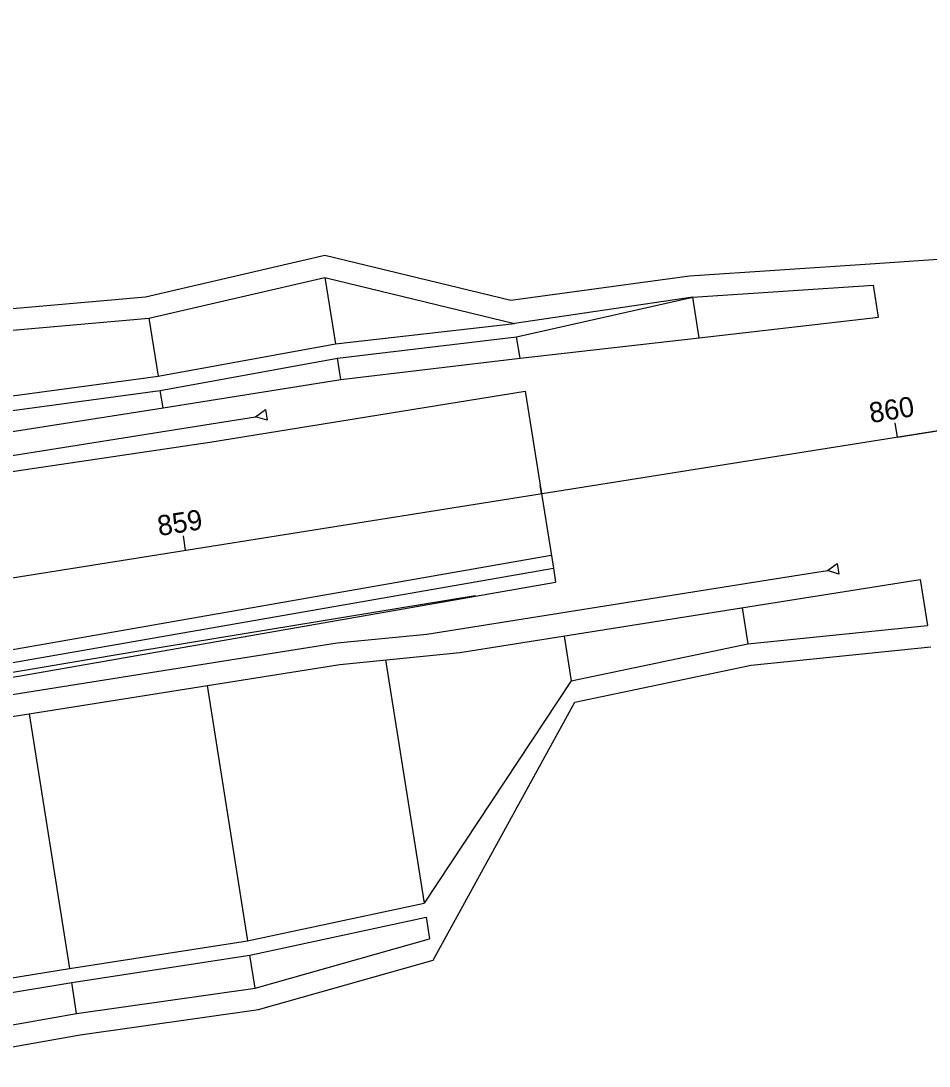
# Model space of a CAD drawing. Extents: x 115987 to 120394, y 324408 to 325987.
# Drawn here: x 117424.6 to 117550.6, y 325408.1 to 325553 of the extents above; entities that cross this region are included whole.
import ezdxf

# ---------------------------------------------------------------- set-up
doc = ezdxf.new("R2010")
doc.units = 0
for name, color, linetype in [('_CIVIL_CONSTRUCTION', 7, 'Continuous'), ('DT_X_Contour_Major', 7, 'Continuous'), ('DT_X_Contour_Minor', 7, 'Continuous'), ('DT_X_Terrain_Boundary', 7, 'Continuous'), ('DT_X_Triangles', 7, 'Continuous'), ('PV_X_EOP', 7, 'Continuous'), ('PV_X_Shoulder', 7, 'Continuous'), ('RW_X_CL_100_Stations', 7, 'Continuous'), ('RW_X_Esmt_LA', 7, 'Continuous'), ('RW_X_Text', 7, 'Continuous'), ('SV_X_Break_Lines', 7, 'Continuous'), ('UT_X_Gas_Cells', 7, 'Continuous')]:
    doc.layers.add(name, color=color, linetype=linetype)

msp = doc.modelspace()

# ---------------------------------------------------------------- linework, layer by layer
at = {"layer": '_CIVIL_CONSTRUCTION'}
msp.add_lwpolyline([(117546.25, 325495.29), (117570.94, 325499.21), (117766.5, 325531.11), (117916.3, 325550), (117982.12, 325552.99), (118061.23, 325550.63), (118140.16, 325542.3), (118267.24, 325523.46), (118330.42, 325512.77)], dxfattribs=at)
at = {"layer": 'DT_X_Contour_Major'}
msp.add_line((117052.43, 325416.91), (117570.94, 325499.21), dxfattribs=at)
at = {"layer": 'DT_X_Contour_Minor'}
for p in [(117498.5, 325477.13), (117400.3, 325457.95)]:
    msp.add_line(p, (117498.82, 325475.16), dxfattribs=at)
at = {"layer": 'DT_X_Terrain_Boundary'}
for p, q in [((117546.25, 325495.29), (117545.93, 325497.26)), ((117496.86, 325487.45), (117496.68, 325488.63)), ((117447.48, 325479.61), (117447.17, 325481.59))]:
    msp.add_line(p, q, dxfattribs=at)
at = {"layer": 'DT_X_Triangles'}
for p, q in [((117494.61, 325501.66), (117496.86, 325487.45)), ((117496.86, 325487.45), (117498.5, 325477.13)), ((117399.7, 325461.7), (117498.22, 325478.91)), ((117399.98, 325459.92), (117498.5, 325477.13))]:
    msp.add_line(p, q, dxfattribs=at)
msp.add_lwpolyline([(117099.65, 325438.36), (117125.38, 325442.42), (117148.92, 325446.09), (117171.45, 325449.83), (117197.23, 325453.75), (117224.14, 325458.05), (117249.57, 325462.07), (117275.34, 325466.27), (117291.59, 325468.95), (117308.28, 325471.78), (117324.97, 325474.61), (117348.76, 325478.42), (117361.44, 325480.5), (117374.12, 325482.58), (117399.9, 325486.47), (117424.04, 325490.6), (117450.84, 325494.57), (117494.61, 325501.66)], dxfattribs=at)
at = {"layer": 'PV_X_EOP'}
for p, q in [((117442.38, 325511.76), (117466.8, 325517.42)), ((117466.8, 325517.42), (117468.26, 325508.22)), ((117466.8, 325517.42), (117493.12, 325511.04)), ((117518.75, 325509.05), (117517.85, 325514.68)), ((117417.41, 325509.58), (117442.38, 325511.76)), ((117442.38, 325511.76), (117443.66, 325503.71)), ((117518.75, 325509.05), (117543.61, 325511.89)), ((117493.88, 325506.21), (117493.41, 325509.18)), ((117493.88, 325506.21), (117518.75, 325509.05)), ((117469.04, 325503.28), (117468.57, 325506.25)), ((117469.04, 325503.28), (117493.88, 325506.21)), ((117444.35, 325499.36), (117469.04, 325503.28)), ((117444.35, 325499.36), (117443.97, 325501.74)), ((117419.66, 325495.45), (117444.35, 325499.36)), ((117485.51, 325465.4), (117549.38, 325475.53)), ((117524.69, 325471.62), (117525.48, 325466.63)), ((117525.48, 325466.63), (117550.39, 325469.15)), ((117500, 325467.7), (117500.99, 325461.49)), ((117468.89, 325463.77), (117485.51, 325465.4)), ((117500.99, 325461.49), (117525.48, 325466.63)), ((117475.21, 325464.39), (117480.56, 325430.68)), ((117234.5, 325426.57), (117468.89, 325463.77)), ((117500.99, 325461.49), (117480.56, 325430.68)), ((117450.46, 325460.85), (117456.08, 325425.43)), ((117425.77, 325456.93), (117431.37, 325421.62)), ((117480.87, 325428.71), (117481.34, 325425.74)), ((117457.12, 325418.86), (117481.34, 325425.74)), ((117457.12, 325418.86), (117456.39, 325423.45)), ((117432.37, 325415.35), (117431.68, 325419.64)), ((117432.37, 325415.35), (117457.12, 325418.86)), ((117407.74, 325411.03), (117432.37, 325415.35))]:
    msp.add_line(p, q, dxfattribs=at)
at = {"layer": 'PV_X_Shoulder'}
for p, q in [((117517.85, 325514.68), (117542.9, 325516.35)), ((117517.85, 325514.68), (117493.12, 325511.04)), ((117493.41, 325509.18), (117517.85, 325514.68)), ((117468.26, 325508.22), (117493.12, 325511.04)), ((117468.57, 325506.25), (117493.41, 325509.18)), ((117443.66, 325503.71), (117468.26, 325508.22)), ((117443.97, 325501.74), (117468.57, 325506.25)), ((117418.87, 325500.38), (117443.66, 325503.71)), ((117419.19, 325498.41), (117443.97, 325501.74)), ((117456.08, 325425.43), (117480.56, 325430.68)), ((117456.39, 325423.45), (117480.87, 325428.71)), ((117431.37, 325421.62), (117456.08, 325425.43)), ((117431.68, 325419.64), (117456.39, 325423.45)), ((117406.71, 325417.56), (117431.37, 325421.62)), ((117407.02, 325415.59), (117431.68, 325419.64))]:
    msp.add_line(p, q, dxfattribs=at)
at = {"layer": 'RW_X_CL_100_Stations'}
for p, q in [((117543.61, 325511.89), (117542.9, 325516.35)), ((117549.38, 325475.53), (117550.39, 325469.15))]:
    msp.add_line(p, q, dxfattribs=at)
at = {"layer": 'RW_X_Esmt_LA'}
for p, q in [((117536.52, 325476.78), (117537.89, 325477.76)), ((117537.89, 325477.76), (117538.12, 325476.28)), ((117480.97, 325467.97), (117530.35, 325475.8)), ((117530.35, 325475.8), (117536.52, 325476.78)), ((117538.12, 325476.28), (117536.52, 325476.78)), ((117468.51, 325466.75), (117480.97, 325467.97)), ((117233.95, 325429.52), (117468.51, 325466.75))]:
    msp.add_line(p, q, dxfattribs=at)
at = {"layer": 'RW_X_Text'}
for p, q in [((117457.2, 325498.11), (117458.57, 325499.09)), ((117458.57, 325499.09), (117458.8, 325497.61)), ((117451.03, 325497.13), (117457.2, 325498.11)), ((117458.8, 325497.61), (117457.2, 325498.11)), ((117401.65, 325489.3), (117451.03, 325497.13))]:
    msp.add_line(p, q, dxfattribs=at)
at = {"layer": 'SV_X_Break_Lines'}
msp.add_lwpolyline([(117201.97, 325427.68), (117227.38, 325431.66), (117252.1, 325435.74), (117280.03, 325440.3), (117292.79, 325442.11), (117309.87, 325444.81), (117326.13, 325447.51), (117353.09, 325451.69), (117415.24, 325461.3), (117441.01, 325465.67), (117487.67, 325473.31)], dxfattribs=at)
at = {"layer": 'UT_X_Gas_Cells'}
for p, q in [((117441.91, 325514.73), (117466.81, 325520.5)), ((117466.81, 325520.5), (117492.61, 325514.25)), ((117517.39, 325517.64), (117542.43, 325519.32)), ((117542.43, 325519.32), (117557.46, 325520.32)), ((117492.61, 325514.25), (117517.39, 325517.64)), ((117416.94, 325512.54), (117441.91, 325514.73)), ((117525.95, 325463.67), (117550.86, 325466.19)), ((117501.46, 325458.52), (117525.95, 325463.67)), ((117481.82, 325422.78), (117501.46, 325458.52)), ((117457.6, 325415.9), (117481.82, 325422.78)), ((117432.84, 325412.39), (117457.6, 325415.9)), ((117408.21, 325408.07), (117432.84, 325412.39))]:
    msp.add_line(p, q, dxfattribs=at)

# ---------------------------------------------------------------- texts
at = {"layer": 'DT_X_Terrain_Boundary'}
for s, p in [('860', (117542.55, 325497.23)), ('859', (117443.81, 325481.56))]:
    msp.add_text(s, height=2.8, rotation=9.0184, dxfattribs=at).set_placement(p)

doc.saveas('drawing.dxf')
